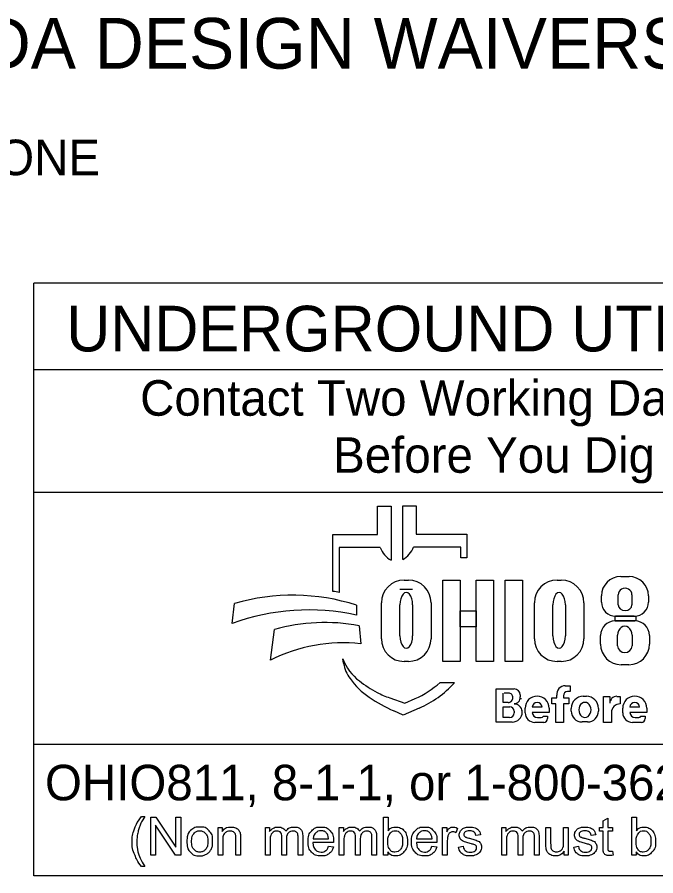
# Model space of a CAD drawing. Extents: x 0 to 34, y 0 to 22.
# Drawn here: x 2.312 to 4.831, y 2.143 to 5.529 of the extents above; entities that cross this region are included whole.
import ezdxf

# ---------------------------------------------------------------- set-up
doc = ezdxf.new("R2010")
doc.units = 0
doc.layers.add('SH_Data', color=7, linetype='Continuous')
doc.layers.add('SH_Text', color=7, linetype='Continuous')

msp = doc.modelspace()

# ---------------------------------------------------------------- linework, layer by layer
at = {"layer": 'SH_Data'}
for p, q in [((2.3775, 2.1428), (2.3775, 4.4803)), ((6.6275, 4.4803), (2.3775, 4.4803)), ((2.3775, 4.1387), (6.6275, 4.1387)), ((2.3775, 3.6553), (6.6275, 3.6553)), ((6.6275, 2.6607), (2.3775, 2.6607)), ((6.6275, 2.1428), (2.3775, 2.1428))]:
    msp.add_line(p, q, dxfattribs=at)
at = {"layer": 'SH_Text'}
for p, q in [((3.7335, 3.4883), (3.7335, 3.5998)), ((3.7335, 3.5998), (3.7872, 3.5998)), ((3.7872, 3.5998), (3.7872, 3.3877)), ((3.8329, 3.39), (3.8329, 3.6021)), ((3.8329, 3.6021), (3.8865, 3.6021)), ((3.8865, 3.6021), (3.8865, 3.4906)), ((3.5576, 3.2644), (3.5576, 3.4883)), ((3.5576, 3.4883), (3.7335, 3.4883)), ((3.8865, 3.4906), (4.0857, 3.4906)), ((4.0857, 3.4906), (4.0857, 3.3968)), ((3.5828, 3.4369), (3.5828, 3.26)), ((3.7439, 3.4369), (3.5828, 3.4369)), ((4.0625, 3.4392), (3.8761, 3.4392)), ((4.0625, 3.3968), (4.0625, 3.4392)), ((4.0857, 3.3968), (4.0625, 3.3968)), ((4.6931, 3.3231), (4.7258, 3.3231)), ((3.8385, 3.3091), (3.8551, 3.3091)), ((4.4416, 3.3091), (4.4581, 3.3091)), ((3.8718, 3.2721), (3.822, 3.2721)), ((4.683, 3.2111), (4.683, 3.2504)), ((4.7371, 3.2504), (4.7371, 3.2111)), ((3.7491, 3.0776), (3.7491, 3.2196)), ((3.9445, 3.2196), (3.9445, 3.0776)), ((4.3521, 3.0776), (4.3521, 3.2196)), ((4.5476, 3.2196), (4.5476, 3.0776)), ((4.6168, 3.2225), (4.6168, 3.2468)), ((4.8022, 3.2468), (4.8022, 3.2225)), ((3.1602, 3.1381), (3.1696, 3.2162)), ((3.6509, 3.2097), (3.6509, 3.1709)), ((3.822, 3.089), (3.822, 3.2114)), ((3.8718, 3.2114), (3.8718, 3.089)), ((4.425, 3.089), (4.425, 3.2114)), ((4.4748, 3.2114), (4.4748, 3.089)), ((4.7462, 3.1665), (4.6728, 3.1665)), ((3.6608, 3.1291), (3.6671, 3.0582)), ((4.671, 3.1482), (4.7483, 3.1482)), ((3.312, 2.9936), (3.3267, 3.1137)), ((4.6131, 3.0563), (4.6131, 3.0903)), ((4.6806, 3.0503), (4.6806, 3.0912)), ((4.7374, 3.0912), (4.7374, 3.0503)), ((4.8062, 3.0903), (4.8062, 3.0563)), ((3.5997, 2.9807), (3.5967, 2.9986)), ((3.8551, 2.9882), (3.8385, 2.9882)), ((4.4581, 2.9882), (4.4416, 2.9882)), ((4.7252, 2.9753), (4.6941, 2.9753)), ((3.98, 2.9048), (4.0375, 2.9048)), ((4.2013, 2.749), (4.2013, 2.8798)), ((4.2013, 2.8798), (4.2725, 2.8798)), ((4.4739, 2.8926), (4.4934, 2.8926)), ((4.4934, 2.8926), (4.4934, 2.8696)), ((3.7816, 2.8444), (3.841, 2.8239)), ((4.2293, 2.8263), (4.2293, 2.8632)), ((4.2545, 2.8632), (4.2332, 2.8632)), ((4.2963, 2.856), (4.2963, 2.8481)), ((4.4213, 2.8212), (4.4213, 2.8442)), ((4.4213, 2.8442), (4.4406, 2.8442)), ((4.4406, 2.8442), (4.4406, 2.8546)), ((4.4667, 2.8526), (4.4667, 2.8442)), ((4.4667, 2.8442), (4.4883, 2.8442)), ((4.4934, 2.8691), (4.4832, 2.8691)), ((4.4883, 2.8442), (4.4883, 2.8212)), ((4.5451, 2.8508), (4.5573, 2.8508)), ((4.6254, 2.7478), (4.6254, 2.8505)), ((4.6254, 2.8505), (4.6499, 2.8505)), ((4.6499, 2.8505), (4.6499, 2.8237)), ((4.6772, 2.8505), (4.691, 2.8505)), ((4.691, 2.8505), (4.691, 2.8209)), ((3.841, 2.8239), (3.8821, 2.8417)), ((4.2487, 2.8263), (4.2293, 2.8263)), ((4.4362, 2.8212), (4.4213, 2.8212)), ((4.4362, 2.7478), (4.4362, 2.8212)), ((4.4883, 2.8212), (4.4667, 2.8212)), ((4.4667, 2.8212), (4.4667, 2.7478)), ((3.835, 2.7769), (3.7976, 2.7934)), ((3.8983, 2.8044), (3.835, 2.7769)), ((4.2293, 2.7669), (4.2293, 2.8097)), ((4.2293, 2.8097), (4.2548, 2.8097)), ((4.2729, 2.7916), (4.2729, 2.7853)), ((4.3043, 2.7887), (4.3043, 2.7884)), ((4.3159, 2.7858), (4.3159, 2.8042)), ((4.3824, 2.8082), (4.3439, 2.8082)), ((4.4104, 2.7866), (4.344, 2.7866)), ((4.4104, 2.8042), (4.4104, 2.7866)), ((4.4973, 2.7922), (4.4973, 2.8029)), ((4.6051, 2.8029), (4.6051, 2.7922)), ((4.6559, 2.786), (4.6559, 2.7478)), ((4.7008, 2.7858), (4.7008, 2.8042)), ((4.7674, 2.8082), (4.7288, 2.8082)), ((4.7953, 2.7866), (4.7289, 2.7866)), ((4.7953, 2.8042), (4.7953, 2.7866)), ((4.265, 2.749), (4.2013, 2.749)), ((4.2546, 2.7669), (4.2293, 2.7669)), ((4.3892, 2.7478), (4.3538, 2.7478)), ((4.3649, 2.7673), (4.379, 2.7673)), ((4.3876, 2.7729), (4.4045, 2.7729)), ((4.4045, 2.7729), (4.4045, 2.7631)), ((4.4667, 2.7478), (4.4362, 2.7478)), ((4.5623, 2.7494), (4.5401, 2.7494)), ((4.6559, 2.7478), (4.6254, 2.7478)), ((4.7742, 2.7478), (4.7388, 2.7478)), ((4.7498, 2.7673), (4.7639, 2.7673)), ((4.7725, 2.7729), (4.7894, 2.7729)), ((4.7894, 2.7729), (4.7894, 2.7631))]:
    msp.add_line(p, q, dxfattribs=at)
for points in [[(3.991, 3.3081), (4.0589, 3.3081), (4.0589, 2.9881), (3.991, 2.9881)], [(4.1231, 3.3081), (4.1911, 3.3081), (4.1911, 2.9881), (4.1231, 2.9881)], [(4.2364, 3.3081), (4.3052, 3.3081), (4.3052, 2.9881), (4.2364, 2.9881)], [(4.0589, 3.1882), (4.1231, 3.1882), (4.1231, 3.1242), (4.0589, 3.1242)], [(4.6706, 3.1665), (4.7523, 3.1665), (4.7523, 3.1481), (4.6706, 3.1481)]]:
    msp.add_lwpolyline(points, close=True, dxfattribs=at)
for points in [[(2.8021, 2.3766), (2.8153, 2.3766)], [(2.8389, 2.2239), (2.8389, 2.3741), (2.8592, 2.3741), (2.9382, 2.2561), (2.9382, 2.3741), (2.9572, 2.3741), (2.9572, 2.2239), (2.9369, 2.2239), (2.8579, 2.3419), (2.8579, 2.2239), (2.8389, 2.2239)], [(3.7743, 2.2239), (3.7573, 2.2239), (3.7573, 2.3741), (3.7757, 2.3741), (3.7757, 2.3206)], [(4.6233, 2.2558), (4.6233, 2.3185), (4.6097, 2.3185), (4.6097, 2.3328), (4.6233, 2.3328), (4.6233, 2.3597), (4.6417, 2.3708), (4.6417, 2.3328), (4.6601, 2.3328), (4.6601, 2.3185), (4.6417, 2.3185), (4.6417, 2.2547)], [(4.7534, 2.2239), (4.7363, 2.2239), (4.7363, 2.3741), (4.7548, 2.3741), (4.7548, 2.3206)], [(3.1048, 2.2239), (3.1048, 2.3328), (3.1214, 2.3328), (3.1214, 2.3173)], [(3.2912, 2.2239), (3.2912, 2.3328), (3.3077, 2.3328), (3.3077, 2.3174)], [(3.5826, 2.2239), (3.5826, 2.3328), (3.5991, 2.3328), (3.5991, 2.3174)], [(3.9904, 2.2239), (3.9904, 2.3328), (4.007, 2.3328), (4.007, 2.3163)], [(4.0495, 2.3293), (4.043, 2.3122)], [(4.1394, 2.3046), (4.1213, 2.3022)], [(4.2236, 2.2239), (4.2236, 2.3328), (4.2401, 2.3328), (4.2401, 2.3174)], [(4.3979, 2.2654), (4.3979, 2.3328), (4.4164, 2.3328), (4.4164, 2.2724)], [(4.4676, 2.2745), (4.4676, 2.3328), (4.4861, 2.3328), (4.4861, 2.2239), (4.4696, 2.2239)], [(4.594, 2.3046), (4.5759, 2.3022)], [(3.1233, 2.2833), (3.1233, 2.2239), (3.1048, 2.2239)], [(3.1932, 2.2908), (3.1932, 2.2239), (3.1748, 2.2239), (3.1748, 2.2901)], [(3.3097, 2.2803), (3.3097, 2.2239), (3.2912, 2.2239)], [(3.3743, 2.2871), (3.3743, 2.2239), (3.3559, 2.2239), (3.3559, 2.2946)], [(3.4388, 2.2986), (3.4388, 2.2239), (3.4203, 2.2239), (3.4203, 2.2924)], [(3.56, 2.2736), (3.4788, 2.2736)], [(3.4799, 2.2887), (3.5406, 2.2887)], [(3.601, 2.2803), (3.601, 2.2239), (3.5826, 2.2239)], [(3.6657, 2.2871), (3.6657, 2.2239), (3.6473, 2.2239), (3.6473, 2.2946)], [(3.7301, 2.2986), (3.7301, 2.2239), (3.7117, 2.2239), (3.7117, 2.2924)], [(3.968, 2.2736), (3.8868, 2.2736)], [(3.8879, 2.2887), (3.9486, 2.2887)], [(4.0088, 2.2809), (4.0088, 2.2239), (3.9904, 2.2239)], [(4.242, 2.2803), (4.242, 2.2239), (4.2236, 2.2239)], [(4.3067, 2.2871), (4.3067, 2.2239), (4.2883, 2.2239), (4.2883, 2.2946)], [(4.3711, 2.2986), (4.3711, 2.2239), (4.3527, 2.2239), (4.3527, 2.2924)], [(3.5404, 2.2591), (3.5595, 2.2567)], [(3.7743, 2.2375), (3.7743, 2.2239)], [(3.9484, 2.2591), (3.9675, 2.2567)], [(4.053, 2.2564), (4.0712, 2.2593)], [(4.4696, 2.2239), (4.4696, 2.24)], [(4.5076, 2.2564), (4.5258, 2.2593)], [(4.6601, 2.2404), (4.6628, 2.2241)], [(4.7534, 2.2375), (4.7534, 2.2239)], [(2.8153, 2.1798), (2.8021, 2.1798)]]:
    msp.add_lwpolyline(points, dxfattribs=at)
for centre, radius, start, end in [((3.8353, 3.4736), 0.0985, 201.9296, 240.7469), ((3.7847, 3.476), 0.0985, 299.2531, 338.0704), ((4.6931, 3.2468), 0.0763, 90, 180), ((4.7258, 3.2468), 0.0763, 0, 90), ((3.8385, 3.2196), 0.0895, 90, 180), ((3.8551, 3.2196), 0.0895, 0, 90), ((4.4416, 3.2196), 0.0895, 90, 180), ((4.4581, 3.2196), 0.0895, 0, 90), ((3.4295, 2.4554), 0.8191, 79.2074, 81.0007), ((3.3997, 2.4302), 0.8191, 72.1402, 106.3144), ((4.6728, 3.2225), 0.056, 180, 270), ((4.7462, 3.2225), 0.056, 270, 0), ((3.4628, 2.2991), 0.8919, 77.8238, 109.8274), ((3.5267, 2.4094), 0.7322, 79.44, 105.8467), ((4.671, 3.0903), 0.0579, 90, 180), ((4.7483, 3.0903), 0.0579, 0, 90), ((3.5987, 2.4262), 0.6357, 83.8248, 116.8021), ((3.8385, 3.0776), 0.0895, 180, 270), ((3.8551, 3.0776), 0.0895, 270, 0), ((4.4416, 3.0776), 0.0895, 180, 270), ((4.4581, 3.0776), 0.0895, 270, 0), ((4.6941, 3.0563), 0.081, 180, 270), ((4.7252, 3.0563), 0.081, 270, 0), ((3.7841, 3.0707), 0.2008, 201.0457, 232.5314), ((3.741, 3.0048), 0.1433, 189.6817, 216.0884), ((3.8747, 3.1022), 0.3088, 216.0884, 235.7167), ((3.9766, 3.3219), 0.5173, 232.5314, 241.794), ((3.7387, 3.1722), 0.3602, 293.4582, 312.0712), ((3.7387, 3.1722), 0.401, 293.4582, 317.8286), ((4.2725, 2.856), 0.0238, 0, 90), ((4.4739, 2.859), 0.0335, 90, 187.5187), ((4.0412, 3.3465), 0.6044, 235.7167, 246.2325), ((3.8914, 3.1631), 0.3371, 241.794, 250.9821), ((4.2487, 2.845), 0.0187, 270, 2.0582), ((4.2505, 2.8463), 0.0169, 357.8325, 90), ((4.2721, 2.8453), 0.0243, 270, 6.6529), ((4.3631, 2.8042), 0.0473, 0, 180), ((4.4832, 2.8526), 0.0165, 90, 180), ((4.5451, 2.8029), 0.0478, 90, 180), ((4.5573, 2.8029), 0.0478, 0, 90), ((4.6768, 2.8237), 0.0269, 89.2449, 180), ((4.7481, 2.8042), 0.0473, 0, 180), ((4.2722, 2.7889), 0.0321, 4.0748, 90), ((4.2827, 2.8438), 0.0175, 347.4023, 0), ((4.3632, 2.8072), 0.0193, 2.9632, 177.0368), ((4.6908, 2.786), 0.0349, 89.6033, 180), ((4.7481, 2.8072), 0.0193, 2.9632, 177.0368), ((4.2546, 2.7853), 0.0184, 270, 0), ((4.2548, 2.7916), 0.0181, 0, 90), ((4.265, 2.7884), 0.0393, 270, 0), ((4.2714, 2.7887), 0.033, 0, 11.7502), ((4.3538, 2.7858), 0.038, 180, 270), ((4.3649, 2.7883), 0.021, 184.827, 270), ((4.5401, 2.7922), 0.0428, 180, 270), ((4.5623, 2.7922), 0.0428, 270, 0), ((4.7388, 2.7858), 0.038, 180, 270), ((4.7498, 2.7883), 0.021, 184.827, 270), ((4.379, 2.7767), 0.00938, 270, 335.9979), ((4.3892, 2.7631), 0.0152, 270, 0), ((4.7639, 2.7767), 0.00938, 270, 335.9979), ((4.7742, 2.7631), 0.0152, 270, 0)]:
    msp.add_arc(centre, radius, start, end, dxfattribs=at)
for centre, major_axis, ratio, start_param, end_param in [((3.8469, 3.2114), (0, 0.0484), 0.514403, 4.712389, 7.853982), ((4.4499, 3.2114), (0, 0.0484), 0.514403, 4.712389, 7.853982), ((4.71, 3.2504), (0.0271, 0), 0.969373, 0, 3.141593), ((4.71, 3.2111), (0.0271, 0), 0.818453, 3.141593, 6.283185), ((4.709, 3.0912), (0, 0.0358), 0.794529, 4.712389, 7.853982), ((3.8469, 3.089), (0, 0.0484), 0.514403, 1.570796, 4.712389), ((4.4499, 3.089), (0, 0.0484), 0.514403, 1.570796, 4.712389), ((4.709, 3.0503), (0.0284, 0), 0.959837, 3.141593, 6.283185), ((4.5517, 2.7976), (0, 0.029), 0.832186, 4.712389, 7.853982), ((4.5517, 2.7976), (0, 0.0302), 0.797287, 1.570796, 4.712389)]:
    msp.add_ellipse(centre, major_axis=major_axis, ratio=ratio, start_param=start_param, end_param=end_param, dxfattribs=at)
for points in [[(2.8021, 2.1798), (2.7869, 2.199), (2.7763, 2.2248), (2.7657, 2.2506), (2.7657, 2.2783), (2.7657, 2.3026), (2.7736, 2.325), (2.7829, 2.3509), (2.8021, 2.3766)], [(2.8153, 2.3766), (2.8029, 2.3553), (2.7989, 2.3462), (2.7927, 2.332), (2.7891, 2.3167), (2.7847, 2.2975), (2.7847, 2.2782), (2.7847, 2.2289), (2.8153, 2.1798)], [(2.9814, 2.2783), (2.9814, 2.3085), (2.9981, 2.3231), (3.0122, 2.3352), (3.0323, 2.3352), (3.0547, 2.3352), (3.069, 2.3205), (3.0832, 2.3058), (3.0832, 2.2799), (3.0832, 2.2589), (3.0769, 2.2469), (3.0706, 2.2348), (3.0586, 2.2282), (3.0466, 2.2215), (3.0323, 2.2215), (3.0095, 2.2215), (2.9954, 2.2362), (2.9814, 2.2508), (2.9814, 2.2783)], [(3.0003, 2.2783), (3.0003, 2.2574), (3.0094, 2.247), (3.0185, 2.2366), (3.0323, 2.2366), (3.046, 2.2366), (3.0551, 2.2471), (3.0642, 2.2575), (3.0642, 2.279), (3.0642, 2.2991), (3.0551, 2.3095), (3.0459, 2.3199), (3.0323, 2.3199), (3.0185, 2.3199), (3.0094, 2.3096), (3.0003, 2.2992), (3.0003, 2.2783)], [(3.1214, 2.3173), (3.1334, 2.3352), (3.156, 2.3352), (3.1659, 2.3352), (3.1741, 2.3316), (3.1823, 2.3281), (3.1864, 2.3224), (3.1905, 2.3166), (3.1922, 2.3087), (3.1932, 2.3036), (3.1932, 2.2908)], [(3.1748, 2.2901), (3.1748, 2.3013), (3.1726, 2.3069), (3.1705, 2.3125), (3.165, 2.3158), (3.1595, 2.3191), (3.1521, 2.3191), (3.1404, 2.3191), (3.1318, 2.3117), (3.1233, 2.3042), (3.1233, 2.2833)], [(3.3077, 2.3174), (3.3128, 2.3254), (3.3214, 2.3303), (3.3299, 2.3352), (3.3407, 2.3352), (3.3528, 2.3352), (3.3606, 2.3301), (3.3683, 2.3251), (3.3715, 2.3161), (3.3844, 2.3352), (3.4051, 2.3352), (3.4213, 2.3352), (3.43, 2.3262), (3.4388, 2.3172), (3.4388, 2.2986)], [(3.3559, 2.2946), (3.3559, 2.3069), (3.3514, 2.313), (3.3469, 2.3191), (3.3366, 2.3191), (3.3288, 2.3191), (3.3222, 2.315), (3.3156, 2.311), (3.3126, 2.3031), (3.3097, 2.2952), (3.3097, 2.2803)], [(3.4203, 2.2924), (3.4203, 2.3035), (3.4185, 2.3083), (3.4168, 2.3132), (3.412, 2.3162), (3.4073, 2.3191), (3.401, 2.3191), (3.3895, 2.3191), (3.3819, 2.3115), (3.3743, 2.3039), (3.3743, 2.2871)], [(3.5595, 2.2567), (3.555, 2.24), (3.5428, 2.2307), (3.5306, 2.2215), (3.5117, 2.2215), (3.4878, 2.2215), (3.4738, 2.2362), (3.4598, 2.2509), (3.4598, 2.2774), (3.4598, 2.3049), (3.474, 2.32), (3.4881, 2.3352), (3.5106, 2.3352), (3.5324, 2.3352), (3.5463, 2.3203), (3.5601, 2.3055), (3.5601, 2.2785), (3.5601, 2.2769), (3.56, 2.2736)], [(3.5406, 2.2887), (3.5394, 2.3025), (3.5337, 2.3094), (3.5249, 2.3201), (3.5108, 2.3201), (3.4981, 2.3201), (3.4894, 2.3115), (3.4808, 2.303), (3.4799, 2.2887)], [(3.5991, 2.3174), (3.6042, 2.3254), (3.6127, 2.3303), (3.6212, 2.3352), (3.6321, 2.3352), (3.6442, 2.3352), (3.6519, 2.3301), (3.6597, 2.3251), (3.6628, 2.3161), (3.6758, 2.3352), (3.6965, 2.3352), (3.7127, 2.3352), (3.7214, 2.3262), (3.7301, 2.3172), (3.7301, 2.2986)], [(3.6473, 2.2946), (3.6473, 2.3069), (3.6428, 2.313), (3.6383, 2.3191), (3.628, 2.3191), (3.6202, 2.3191), (3.6136, 2.315), (3.607, 2.311), (3.604, 2.3031), (3.601, 2.2952), (3.601, 2.2803)], [(3.7117, 2.2924), (3.7117, 2.3035), (3.7099, 2.3083), (3.7081, 2.3132), (3.7034, 2.3162), (3.6987, 2.3191), (3.6923, 2.3191), (3.6809, 2.3191), (3.6733, 2.3115), (3.6657, 2.3039), (3.6657, 2.2871)], [(3.7741, 2.2792), (3.7741, 2.2596), (3.7794, 2.2509), (3.7881, 2.2366), (3.8029, 2.2366), (3.815, 2.2366), (3.8238, 2.2471), (3.8326, 2.2576), (3.8326, 2.2784), (3.8326, 2.2998), (3.8241, 2.3099), (3.8157, 2.3201), (3.8038, 2.3201), (3.7917, 2.3201), (3.7829, 2.3096), (3.7741, 2.299), (3.7741, 2.2792)], [(3.7757, 2.3206), (3.7874, 2.3352), (3.8055, 2.3352), (3.8155, 2.3352), (3.8245, 2.3311), (3.8335, 2.3271), (3.8392, 2.3198), (3.845, 2.3124), (3.8483, 2.3021), (3.8516, 2.2918), (3.8516, 2.28), (3.8516, 2.252), (3.8378, 2.2368), (3.8239, 2.2215), (3.8046, 2.2215), (3.7853, 2.2215), (3.7743, 2.2375)], [(3.9675, 2.2567), (3.963, 2.24), (3.9508, 2.2307), (3.9386, 2.2215), (3.9196, 2.2215), (3.8958, 2.2215), (3.8818, 2.2362), (3.8678, 2.2509), (3.8678, 2.2774), (3.8678, 2.3049), (3.882, 2.32), (3.8961, 2.3352), (3.9186, 2.3352), (3.9404, 2.3352), (3.9543, 2.3203), (3.9681, 2.3055), (3.9681, 2.2785), (3.9681, 2.2769), (3.968, 2.2736)], [(3.9486, 2.2887), (3.9474, 2.3025), (3.9417, 2.3094), (3.9328, 2.3201), (3.9188, 2.3201), (3.9061, 2.3201), (3.8974, 2.3115), (3.8888, 2.303), (3.8879, 2.2887)], [(4.007, 2.3163), (4.0133, 2.3278), (4.0187, 2.3315), (4.0241, 2.3352), (4.0305, 2.3352), (4.0398, 2.3352), (4.0495, 2.3293)], [(4.043, 2.3122), (4.0363, 2.3162), (4.0295, 2.3162), (4.0235, 2.3162), (4.0187, 2.3125), (4.0139, 2.3089), (4.0119, 2.3024), (4.0088, 2.2926), (4.0088, 2.2809)], [(4.1213, 2.3022), (4.1201, 2.3106), (4.1142, 2.3153), (4.1083, 2.3201), (4.0975, 2.3201), (4.0848, 2.3201), (4.0794, 2.3159), (4.0739, 2.3116), (4.0739, 2.306), (4.0739, 2.3024), (4.0762, 2.2995), (4.0785, 2.2966), (4.0833, 2.2946), (4.086, 2.2936), (4.0996, 2.2899), (4.1192, 2.2847), (4.1269, 2.2813), (4.1347, 2.278), (4.1391, 2.2717), (4.1435, 2.2653), (4.1435, 2.2559), (4.1435, 2.2467), (4.1381, 2.2386), (4.1327, 2.2304), (4.1226, 2.226), (4.1124, 2.2215), (4.0996, 2.2215), (4.0784, 2.2215), (4.0672, 2.2303), (4.0561, 2.2391), (4.053, 2.2564)], [(4.0712, 2.2593), (4.0727, 2.2483), (4.0798, 2.2425), (4.0868, 2.2366), (4.0995, 2.2366), (4.1122, 2.2366), (4.1184, 2.2418), (4.1245, 2.247), (4.1245, 2.254), (4.1245, 2.2602), (4.1191, 2.2638), (4.1153, 2.2663), (4.1002, 2.2701), (4.0799, 2.2752), (4.072, 2.2789), (4.0642, 2.2827), (4.0601, 2.2893), (4.0561, 2.2959), (4.0561, 2.3038), (4.0561, 2.3111), (4.0594, 2.3173), (4.0628, 2.3235), (4.0685, 2.3276), (4.0728, 2.3308), (4.0803, 2.333), (4.0877, 2.3352), (4.0962, 2.3352), (4.109, 2.3352), (4.1187, 2.3315), (4.1284, 2.3278), (4.133, 2.3215), (4.1377, 2.3152), (4.1394, 2.3046)], [(4.2401, 2.3174), (4.2452, 2.3254), (4.2537, 2.3303), (4.2622, 2.3352), (4.2731, 2.3352), (4.2852, 2.3352), (4.2929, 2.3301), (4.3007, 2.3251), (4.3038, 2.3161), (4.3168, 2.3352), (4.3375, 2.3352), (4.3537, 2.3352), (4.3624, 2.3262), (4.3711, 2.3172), (4.3711, 2.2986)], [(4.2883, 2.2946), (4.2883, 2.3069), (4.2838, 2.313), (4.2793, 2.3191), (4.269, 2.3191), (4.2612, 2.3191), (4.2546, 2.315), (4.248, 2.311), (4.245, 2.3031), (4.242, 2.2952), (4.242, 2.2803)], [(4.3527, 2.2924), (4.3527, 2.3035), (4.3509, 2.3083), (4.3491, 2.3132), (4.3444, 2.3162), (4.3397, 2.3191), (4.3333, 2.3191), (4.3219, 2.3191), (4.3143, 2.3115), (4.3067, 2.3039), (4.3067, 2.2871)], [(4.5759, 2.3022), (4.5747, 2.3106), (4.5688, 2.3153), (4.5629, 2.3201), (4.5521, 2.3201), (4.5394, 2.3201), (4.5339, 2.3159), (4.5285, 2.3116), (4.5285, 2.306), (4.5285, 2.3024), (4.5308, 2.2995), (4.533, 2.2966), (4.5378, 2.2946), (4.5406, 2.2936), (4.5542, 2.2899), (4.5737, 2.2847), (4.5815, 2.2813), (4.5893, 2.278), (4.5937, 2.2717), (4.5981, 2.2653), (4.5981, 2.2559), (4.5981, 2.2467), (4.5927, 2.2386), (4.5873, 2.2304), (4.5772, 2.226), (4.567, 2.2215), (4.5542, 2.2215), (4.5329, 2.2215), (4.5218, 2.2303), (4.5107, 2.2391), (4.5076, 2.2564)], [(4.5258, 2.2593), (4.5273, 2.2483), (4.5343, 2.2425), (4.5414, 2.2366), (4.554, 2.2366), (4.5668, 2.2366), (4.5729, 2.2418), (4.5791, 2.247), (4.5791, 2.254), (4.5791, 2.2602), (4.5736, 2.2638), (4.5698, 2.2663), (4.5548, 2.2701), (4.5345, 2.2752), (4.5266, 2.2789), (4.5188, 2.2827), (4.5147, 2.2893), (4.5107, 2.2959), (4.5107, 2.3038), (4.5107, 2.3111), (4.514, 2.3173), (4.5173, 2.3235), (4.5231, 2.3276), (4.5274, 2.3308), (4.5348, 2.333), (4.5423, 2.3352), (4.5508, 2.3352), (4.5636, 2.3352), (4.5733, 2.3315), (4.583, 2.3278), (4.5876, 2.3215), (4.5922, 2.3152), (4.594, 2.3046)], [(4.7532, 2.2792), (4.7532, 2.2596), (4.7585, 2.2509), (4.7672, 2.2366), (4.782, 2.2366), (4.7941, 2.2366), (4.8029, 2.2471), (4.8116, 2.2576), (4.8116, 2.2784), (4.8116, 2.2998), (4.8032, 2.3099), (4.7948, 2.3201), (4.7828, 2.3201), (4.7708, 2.3201), (4.762, 2.3096), (4.7532, 2.299), (4.7532, 2.2792)], [(4.7548, 2.3206), (4.7664, 2.3352), (4.7846, 2.3352), (4.7946, 2.3352), (4.8036, 2.3311), (4.8125, 2.3271), (4.8183, 2.3198), (4.8241, 2.3124), (4.8274, 2.3021), (4.8306, 2.2918), (4.8306, 2.28), (4.8306, 2.252), (4.8168, 2.2368), (4.803, 2.2215), (4.7836, 2.2215), (4.7644, 2.2215), (4.7534, 2.2375)], [(3.4788, 2.2736), (3.4799, 2.2557), (3.489, 2.2462), (3.4981, 2.2366), (3.5117, 2.2366), (3.5219, 2.2366), (3.5291, 2.242), (3.5362, 2.2473), (3.5404, 2.2591)], [(3.8868, 2.2736), (3.8879, 2.2557), (3.897, 2.2462), (3.9061, 2.2366), (3.9197, 2.2366), (3.9299, 2.2366), (3.937, 2.242), (3.9442, 2.2473), (3.9484, 2.2591)], [(4.4164, 2.2724), (4.4164, 2.258), (4.4175, 2.253), (4.4192, 2.2457), (4.4249, 2.2416), (4.4305, 2.2374), (4.4388, 2.2374), (4.4471, 2.2374), (4.4543, 2.2417), (4.4616, 2.2459), (4.4646, 2.2533), (4.4676, 2.2606), (4.4676, 2.2745)], [(4.4696, 2.24), (4.4569, 2.2215), (4.4351, 2.2215), (4.4255, 2.2215), (4.4171, 2.2252), (4.4088, 2.2289), (4.4047, 2.2345), (4.4007, 2.2401), (4.3991, 2.2482), (4.3979, 2.2536), (4.3979, 2.2654)], [(4.6628, 2.2241), (4.655, 2.2224), (4.6488, 2.2224), (4.6388, 2.2224), (4.6333, 2.2256), (4.6278, 2.2288), (4.6255, 2.234), (4.6233, 2.2392), (4.6233, 2.2558)], [(4.6417, 2.2547), (4.6417, 2.2468), (4.6427, 2.2445), (4.6436, 2.2423), (4.6458, 2.2409), (4.648, 2.2396), (4.6521, 2.2396), (4.6551, 2.2396), (4.6601, 2.2404)]]:
    msp.add_open_spline(points, degree=3, dxfattribs=at)

# ---------------------------------------------------------------- texts
for s, height, p in [('ADA DESIGN WAIVERS', 0.2, (1.9944, 5.3256)), ('  NONE', 0.14, (1.9944, 4.9056)), ('UNDERGROUND UTILITIES', 0.18, (2.5057, 4.2106)), ('Contact Two Working Days', 0.14, (2.7972, 3.9571)), ('Before You Dig', 0.14, (3.5583, 3.7321)), ('OHIO811, 8-1-1, or 1-800-362-2764', 0.14, (2.422, 2.4406))]:
    msp.add_text(s, height=height, dxfattribs=at).set_placement(p)

doc.saveas('drawing.dxf')
